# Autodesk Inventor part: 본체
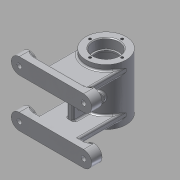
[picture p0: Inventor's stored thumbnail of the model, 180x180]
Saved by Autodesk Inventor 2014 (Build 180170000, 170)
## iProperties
Created: 2015-11
Part Number: 본체
Material: 알루미늄 6061
Document SubType Name: Modeling
Designer: L10
Density: 2.71 g/cm^3
Appearance: 알루미늄 - 평지
Mass: 358.802 g
Surface Area: 460.446 cm^2
Volume: 132.399 cm^3
Author: L10
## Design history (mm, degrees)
sketch "스케치1"
  geometry: L1 (0, 35)-(0, -35); L2 (25, -35)-(25, 0); L3 (25, -35)-(16, -35); L4 (16, -35)-(16, -23); L5 (16, -23)-(14, -23); L6 (14, -23)-(14, -21); L7 (14, -21)-(21, -21); L8 (21, -21)-(21, 0); L9 (21, 0)-(25, 0); 3 further points
  constraints: 18 end point, 4 parallel, 4 perpendicular, 2 midpoint, 1 coincident, 1 horizontal alignment, 1 vertical
  dimensions: "d0" = 70 distance of L1.start L1.end; "d1" = 50 diameter of L2 L1; "d2" = 32 diameter of L4 L1; "d3" = 28 diameter of L6 L1; "d4" = 42 diameter of L8 L1; "d5" = 2 distance of L5.end L6.end; "d6" = 12 distance of L3.end L4.end; "d7" = 35 distance of L2.start L2.end
revolve "회전1" sketch "스케치1" stored, may be unused: angle "d8" = 90 deg
node "작업 평면2"
sketch "스케치2"
  geometry: L1 (-25, 0)-(25, 0); L2 (25, 0)-(25, -68); L3 (25, -68)-(-25, -68); L4 (-25, -68)-(-25, 0); C1 r 25 at (0, 0) reference; A1 r 25 centre (0, 0) between (-25, 0) and (25, 0); 3 further points
  constraints: 8 end point, 2 coincident, 2 midpoint, 2 parallel, 2 point on circle, 1 centre point, 1 horizontal, 1 perpendicular, 1 vertical alignment
  dimensions: "d11" = 68 distance from line of L3 point (0, 0); "d12" = 50 distance of L2.end L3.end
extrude "돌출1" join sketch "스케치2" distance "d13" = 8; taper "d14" = 0 deg
sketch "스케치3"
  geometry: L1 (0, 0)-(50, 0) reference; L2 (50, 0)-(50, 8) reference; L3 (0, 8)-(50, 8) reference; L4 (0, 0)-(0, 8) reference; L5 (-15, 8)-(65, 8); L6 (65, 8)-(65, -12); L7 (65, -12)-(-15, -12); L8 (-15, -12)-(-15, 8); 6 further points
  constraints: 8 end point, 5 midpoint, 2 coincident, 2 parallel, 2 vertical alignment, 1 horizontal, 1 perpendicular, 4 other
  dimensions: "d15" = 80 distance of L5.start L5.end; "d16" = 20 distance of L7.end L5.start
extrude "돌출2" join sketch "스케치3" distance "d17" = 10; taper "d18" = 0 deg
extrude "돌출3" join sketch "스케치3" distance "d19" = 13; taper "d20" = 0 deg
hole "구멍1" diameter "d23" = 6; stored, may be unused: countersink angle "d27" = 90 deg, drill point angle "d29" = 118 deg; dims "d21" = 10, "d22" = 10, "d24" = 6, "d25" = 12, "d26" = 4, "d28" = 13
chamfer "모따기1" distance "d30" = 1; stored, may be unused: second distance "d31" = 2, angle "d32" = 45 deg
sketch "스케치4"
  geometry: L1 (-25, -20)-(-45, -20); L2 (-45, -20)-(-45, 20); L3 (-45, 20)-(-25, 20); L4 (-25, 20)-(-25, -20); L5 (0, 20)-(-58, 20) reference; L6 (0, -20)-(-58, -20) reference; L7 (-25, 35)-(-25, -35) reference; L8 (-31.5, 8)-(-38.5, 8); L9 (-38.5, 8)-(-38.5, -8); L10 (-38.5, -8)-(-31.5, -8); L11 (-31.5, -8)-(-31.5, 8); C1 r 3.5 at (-35, -8); 6 further points
  constraints: 16 end point, 7 midpoint, 4 parallel, 2 horizontal, 2 horizontal alignment, 2 perpendicular, 1 centre point, 1 point on line, 1 tangent, 1 vertical alignment, 2 other
  dimensions: "d34" = 20 distance between parallel lines of L2 L7; "d36" = 23 dimension on C1; "d38" = 3.5 radius of C1
extrude "돌출4" join sketch "스케치4" stored distance "d39" = 8; taper "d40" = 0 deg
node "작업 평면4"
sketch "스케치6"
  geometry: C1 r 5 at (0, 0); 1 further point
  constraints: 1 centre point, 1 coincident
  dimensions: "d45" = 10 diameter of C1
extrude "돌출6" join sketch "스케치6" stored distance "d46" = 28; taper "d47" = 0 deg
hole "구멍2" diameter "d50" = 5.188; stored, may be unused: countersink angle "d54" = 90 deg, drill point angle "d56" = 0 deg; dims "d48" = 10, "d49" = 10, "d51" = 6, "d52" = 12, "d53" = 4, "d55" = 13
sketch "스케치7"
  geometry: L1 (0, 0)-(14, -24.249); L2 (0, 47.2)-(0, -87.2) reference; L3 (14, -24.249)-(19.196, -21.249); L4 (19.196, -21.249)-(17.331, -18.018); L5 (14, -24.249)-(12.5, -21.651); A1 r 25 centre (0, 0) between (0, -25) and (25, 0) reference
  constraints: 8 end point, 2 perpendicular, 2 point on circle, 1 point on line
  dimensions: "d57" = 30 deg angle of L1 L2; "d58" = 28 distance of L1.start L1.end; "d59" = 12 diameter of L4 L1
revolve "회전2" sketch "스케치7" stored, may be unused: angle "d60" = 90 deg
hole "구멍3" diameter "d63" = 5.188; stored, may be unused: countersink angle "d67" = 90 deg, drill point angle "d69" = 0 deg; dims "d61" = 10, "d62" = 10, "d64" = 6, "d65" = 12, "d66" = 4, "d68" = 13
sketch "스케치8"
  geometry: L1 (0, 0)-(0, 40) reference; L2 (4, 0)-(0, 0) reference; L3 (4, 40)-(4, 0) reference; L4 (0, 40)-(4, 40) reference; L5 (4, 0)-(4, 40) reference; L6 (-4, 0)-(4, 0) reference; L7 (-4, 40)-(-4, 0) reference; L8 (4, 40)-(-4, 40) reference; L9 (-4, 40)-(4, 40); L10 (4, 40)-(4, 0); L11 (4, 0)-(-4, 0); L12 (-4, 0)-(-4, 40); 1 further point
  constraints: 8 end point, 2 parallel, 1 horizontal, 1 perpendicular
extrude "돌출7" join sketch "스케치8" stored distance "d75" = 28; taper "d76" = 0 deg
fillet "모깎기1" dims "d70" = 0.3, "d71" = 0.3
fillet "모깎기2" dims "d72" = 3
fillet "모깎기3" dims "d73" = 2
fillet "모깎기4" dims "d74" = 2
fillet "모깎기5" dims "d77" = 2
chamfer "모따기6" distance "d90" = 1; stored, may be unused: second distance "d91" = 2, angle "d92" = 45 deg
chamfer "모따기7" distance "d93" = 1; stored, may be unused: second distance "d94" = 2, angle "d95" = 45 deg
sketch "스케치9" dims "d96" = 40
  geometry: C1 r 25 at (0, 0) reference; C2 r 17 at (0, 0) reference; 2 further points
  constraints: 2 vertical alignment, 1 coincident, 2 other
hole "구멍4" sketch "스케치9" at (0, 20) diameter "d97" = 3.242; stored, may be unused: countersink angle "d101" = 90 deg, drill point angle "d103" = 118 deg; dims "d98" = 8, "d99" = 12, "d100" = 4, "d102" = 10
chamfer "모따기8" distance "d107" = 1; stored, may be unused: second distance "d108" = 2, angle "d109" = 45 deg
chamfer "모따기9" distance "d110" = 1; stored, may be unused: second distance "d111" = 2, angle "d112" = 45 deg
node "작업 평면5"
sketch "스케치11"
  geometry: L1 (25, 35)-(25, -35) reference; 2 further points
  constraints: 1 horizontal alignment, 1 midpoint
node "작업 평면6"
sketch "스케치12"
  geometry: L1 (-25, 35)-(-25, -35) reference; L2 (-25, -35)-(25, -35) reference; 2 further points
  constraints: 1 other
  dimensions: "d114" = 25 distance from line of point (0, 0) L1; "d115" = 35 distance from line of L2 point (0, 0)
feature "엠보싱1" sketch "스케치12" dims "d0" = 70, "d1" = 50, "d2" = 32, "d3" = 28, "d4" = 42, "d5" = 2, "d6" = 12, "d7" = 35, "d11" = 68, "d12" = 50, "d116" = 0.5, "d117" = 0
node "솔리드1"
mirror "대칭1"
mirror "대칭2"
pattern_circular "원형 패턴1" dims angle "d105" = 360 deg
mirror "대칭3"
node "투영된 루프1"
other parameters: "d10" = -28, "d44" = 28, "d113" = -25
